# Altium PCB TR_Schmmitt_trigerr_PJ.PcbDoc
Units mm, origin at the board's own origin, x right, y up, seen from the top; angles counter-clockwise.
Board outline 45 x 30 mm, 2 copper layers (Top Layer, Bottom Layer); 16 components, 13 nets, 36 pads, 0 vias.
Unrouted connection lines stored in the file: 2.
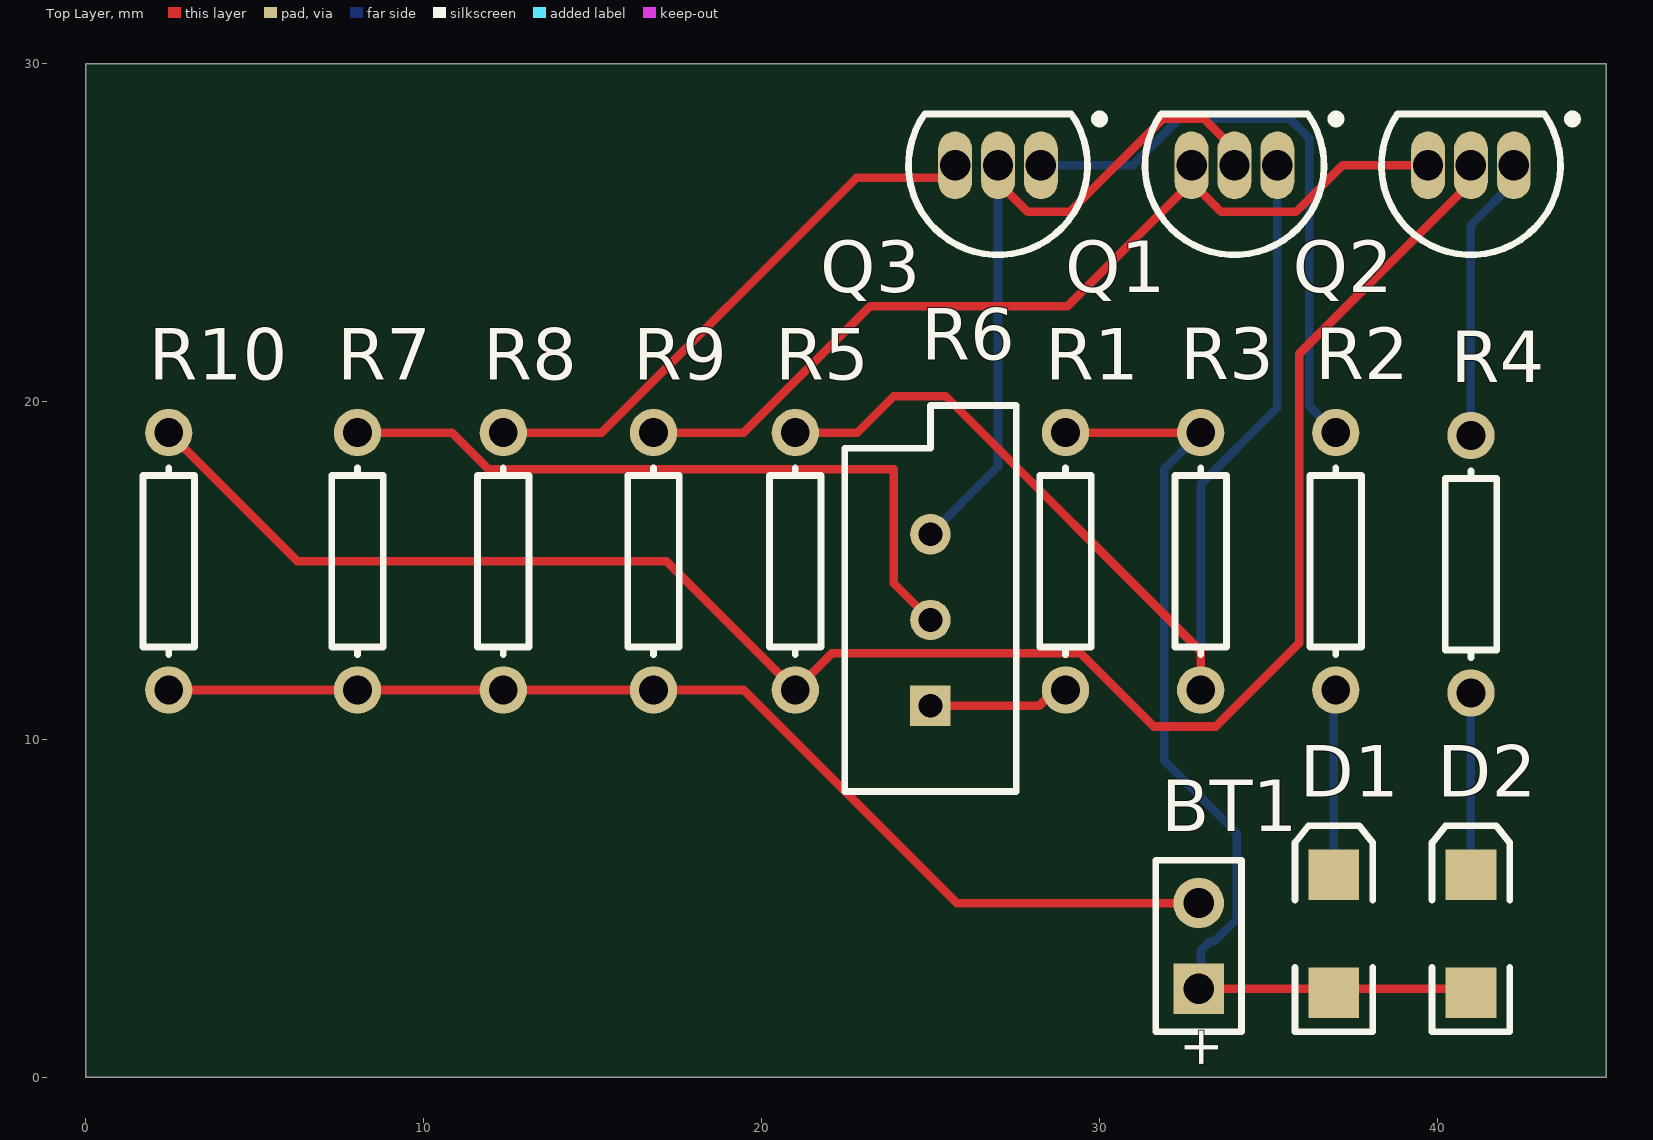
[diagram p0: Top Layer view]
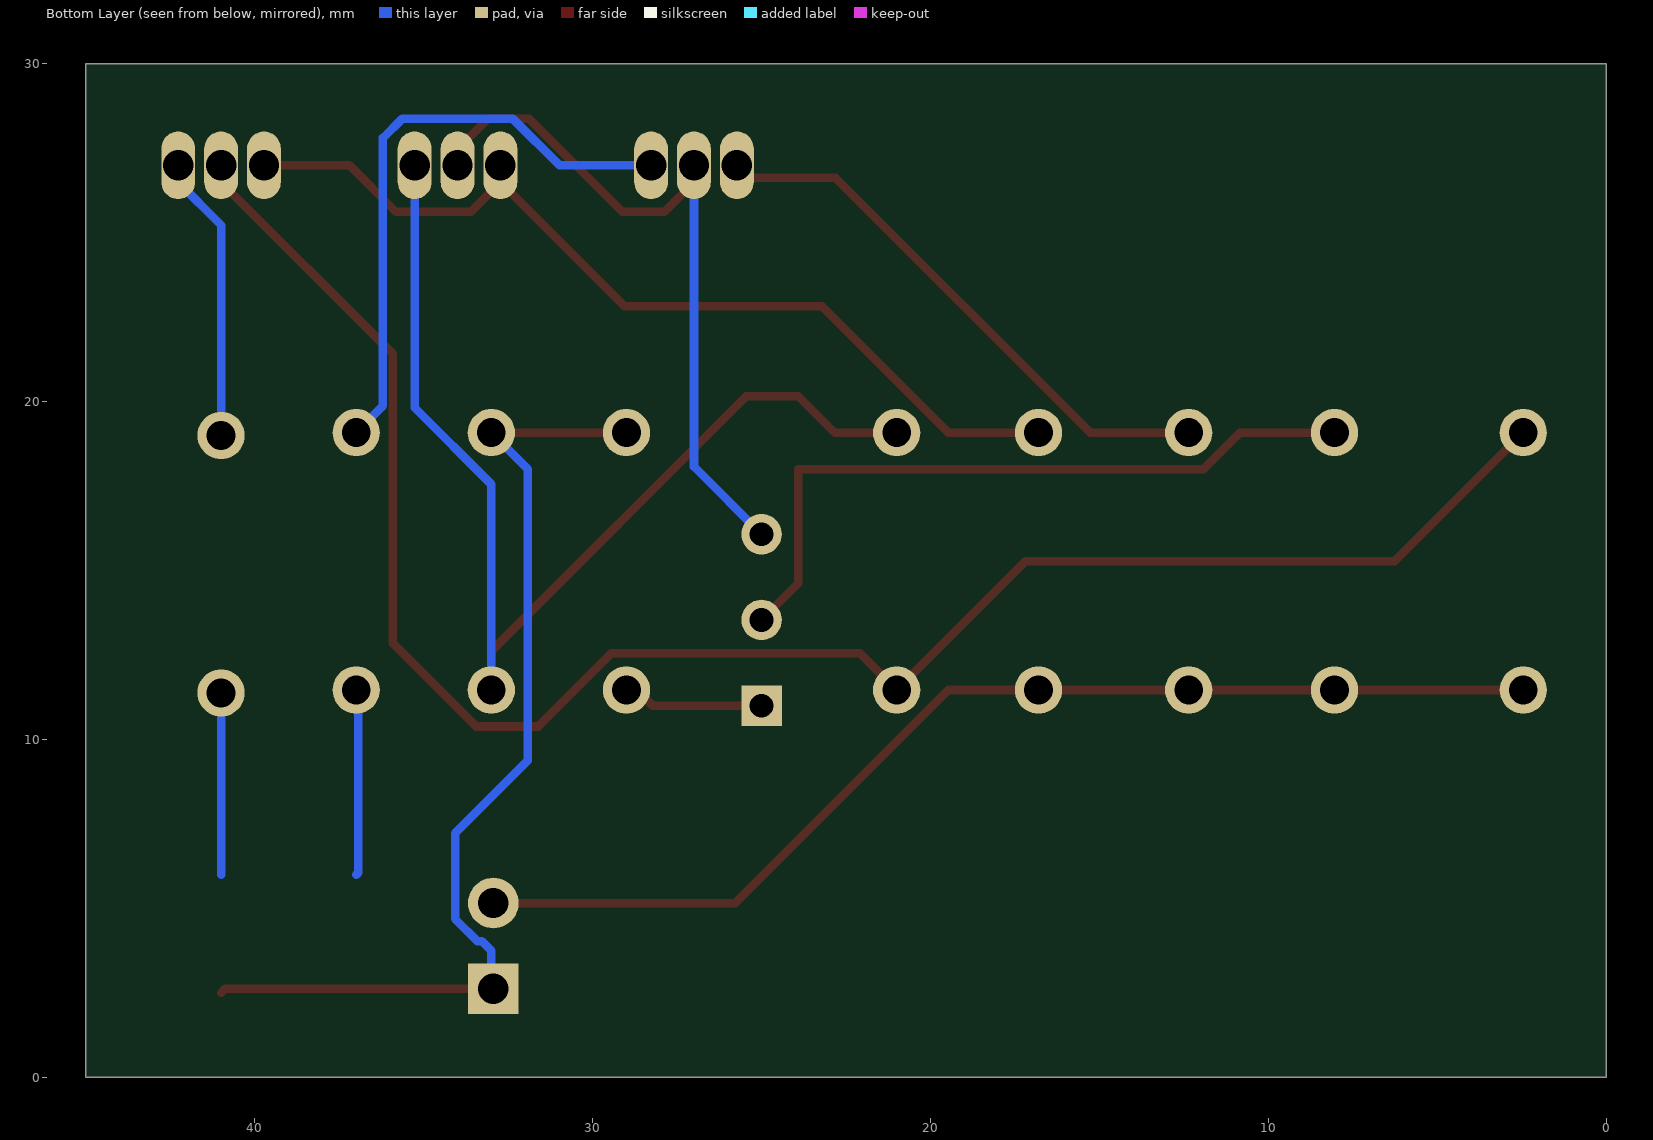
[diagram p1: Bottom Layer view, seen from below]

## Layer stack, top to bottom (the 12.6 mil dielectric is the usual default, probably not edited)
Top Solder: solder mask 0.0102, Solder Resist, Dk 3.5
Top Layer: signal copper 0.0356
Dielectric 1: dielectric 0.32, FR-4, Dk 4.8
Bottom Layer: signal copper 0.0356
Bottom Solder: solder mask 0.0102, Solder Resist, Dk 3.5

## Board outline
0,0 0,30 45,30 45,0

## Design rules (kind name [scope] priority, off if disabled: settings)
Clearance [All] p1: gap=0.254 ignorepadtopadclearanceinfootprint=FALSE except(0: Arc-Hole Track-Hole SMDPad-Hole THPad-Hole Via-Hole Fill-Hole Poly-Hole Region-Hole Text-Hole)
PolygonConnect [All] p1: connectstyle=Relief reliefconductorwidth=0.254 reliefentries=4 polygonreliefangle="90 Angle" airgapwidth=0.254
RoutingVias [All] p1: holewidth=0.711 width=1.27 viastyle="Through Hole" minholewidth=0.711 minwidth=1.27 maxholewidth=0.711 maxwidth=1.27
SolderMaskExpansion [All] p1: expansion=0.102 istentingtop=FALSE
Width [All] p1: maxlimit=0.254 minlimit=0.254 preferedwidth=0.254
30 further rules are at their usual default settings.

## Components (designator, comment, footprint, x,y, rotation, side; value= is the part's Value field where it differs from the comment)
BT1 "Battery" BAT-2 32.941,3.89 r90 top
D1 "RED" 3.2X1.6X1.1 36.941,4.25 r90 top
D2 "GREEN" 3.2X1.6X1.1 41,4.25 r90 top
Q1 "NPN" TO-226-AA 34,27 r90 top
Q2 "NPN" TO-226-AA 41,27 r90 top
Q3 "NPN" TO-226-AA 27,27 r90 top
R1 "Res1" AXIAL-0.3 29,15.278 r90 top value=22K
R2 "Res1" AXIAL-0.3 37,15.278 r270 top value=220
R3 "Res1" AXIAL-0.3 33,15.278 r90 top value=220
R4 "Res1" AXIAL-0.3 41,15.19 r270 top value=330
R5 "Res1" AXIAL-0.3 21,15.278 r90 top value=10K
R6 "RPot" VR5 25,13.54 r90 top value=1K
R7 "Res1" AXIAL-0.3 8.038,15.278 r90 top value=1K
R8 "Res1" AXIAL-0.3 12.356,15.278 r90 top value=120
R9 "Res1" AXIAL-0.3 16.801,15.278 r90 top value=100
R10 "Res1" AXIAL-0.3 2.45,15.278 r90 top value=3.9K

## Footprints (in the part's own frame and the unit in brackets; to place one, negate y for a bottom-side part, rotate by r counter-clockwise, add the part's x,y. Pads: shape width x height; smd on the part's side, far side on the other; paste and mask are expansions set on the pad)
3.2X1.6X1.1 [mm] "SMT LED; 2 Flat Leads"
  rect 1.5x1.5 smd: 1(-1.75,0) 2(1.75,0)
  silkscreen extent -2.9,-1.15 3.2,1.15
AXIAL-0.3 [mm] "Axial Device, Thru-Hole; 2 Leads; 0.3 in Pin Spacing"
  round 1.4 hole 0.85: 1(-3.81,0) 2(3.81,0)
  silkscreen extent -2.77,-0.76 2.77,0.76
BAT-2 [mm] "Battery; 2 Leads"
  rect 1.5x1.5 hole 0.9: 1(-1.27,0)
  round 1.5 hole 0.9: 2(1.27,0)
  silkscreen extent -2.54,-1.27 2.54,1.27
TO-226-AA [mm] "TO, Flat Index; 3 In-Line, Axial Leads; Body Dia. 4.8mm; Leads 0.55 x 0.51 mm (max)"
  oval 2x1 hole 0.9: 1(0,-1.27) 2(0,0) 3(0,1.27)
  silkscreen extent -2.65,-3.13 1.52,2.65, body extent -2.65,-2.66 1.52,2.66, height 5.33
VR5 [mm] "Thru-Hole; 3 Leads"
  rect 1.2x1.2 hole 0.7: 1(-2.54,0)
  round 1.2 hole 0.7: 2(0,0) 3(2.54,0)
  silkscreen extent -5.08,-2.54 6.35,2.54

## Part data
BT1: "Multicell Battery"
D1 D2: library part LED0, "Typical INFRARED GaAs LED"
Q1 Q2 Q3: "NPN Bipolar Transistor"
R1 R2 R3 R4 R5 R7 R8 R9 R10: "Resistor"
R6: "Potentiometer"

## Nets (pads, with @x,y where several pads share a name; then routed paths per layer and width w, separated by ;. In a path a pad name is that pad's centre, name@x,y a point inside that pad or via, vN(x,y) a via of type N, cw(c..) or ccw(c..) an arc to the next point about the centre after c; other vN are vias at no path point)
GND: BT1.2 R7.1 R8.1 R9.1 R10.1 | length 33.1
  Top Layer w0.254: R10.1 R7.1 R8.1 R9.1 19.471,11.468 25.779,5.16 BT1.2
NetD1_2: D1.2 R2.2 | length 5.5
  Bottom Layer w0.254: 37,6 36.941,6.059 36.941,11.409 R2.2
NetD2_2: D2.2 R4.2 | length 5.4
  Bottom Layer w0.254: 41,6 R4.2
NetQ1_1: Q1.1 R3.1 R5.2 | length 33.2
  Top Layer w0.254: R5.2 22.838,19.088 23.919,20.169 25.448,20.169 33,12.617 R3.1
  Bottom Layer w0.254: R3.1 33,17.559 35.27,19.829 Q1.1
NetQ1_2: Q1.2 Q3.2 R6.3 | length 21.6
  Top Layer w0.254: Q3.2 27,26.5 27.881,25.619 29.119,25.619 31.881,28.381 33.095,28.381 34,27.476 Q1.2
  Bottom Layer w0.254: R6.3 27,18.08 Q3.2
NetQ1_3: Q1.3 Q2.3 R9.2 | length 27.4
  Top Layer w0.254: R9.2 19.471,19.088 23.216,22.832 29.062,22.832 Q1.3@32.73,26.5 ; Q1.3 Q1.3@32.73,26.5 ; Q2.3 37.201,27 35.82,25.619 33.611,25.619 Q1.3@32.73,26.5
NetQ2_1: Q2.1 R4.1 | length 8.5
  Bottom Layer w0.254: R4.1 41,25.23 42.27,26.5 Q2.1
NetQ2_2: Q2.2 R5.1 R10.2 | length 55.2
  Top Layer w0.254: R10.2 6.26,15.278 17.19,15.278 R5.1 22.081,12.549 29.448,12.549 31.61,10.387 33.448,10.387 35.919,12.858 35.919,21.419 41,26.5 Q2.2
NetQ3_1: Q3.1 R2.1 | length 17.9
  Top Layer w0.254: R2.1 R2.1@37.088,19.088
  Bottom Layer w0.254: Q3.1 30.984,27 32.365,28.381 35.635,28.381 36.208,27.808 36.208,19.88 R2.1
NetQ3_3: Q3.3 R8.2 | length 16.7
  Top Layer w0.254: R8.2 15.272,19.088 22.811,26.627 25.385,26.627 25.73,26.972 Q3.3
NetR1_1: R1.1 R6.1 | length 4.2
  Top Layer w0.254: R6.1 28.222,11 28.69,11.468 R1.1
NetR6_2: R6.2 R7.2 | length 21.2
  Top Layer w0.254: R7.2 10.827,19.088 11.908,18.007 23.919,18.007 23.919,14.621 R6.2
VCC: BT1.1 D1.1 D2.1 R1.2 R3.2 | length 30.5
  Top Layer w0.254: R1.2 R3.2 ; BT1.1 40.88,2.62 D2.1
  Bottom Layer w0.254: BT1.1 33,2.679 33,3.751 33.278,4.029 33.409,4.029 34.072,4.692 34.072,7.227 31.919,9.38 31.919,18.007 R3.2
